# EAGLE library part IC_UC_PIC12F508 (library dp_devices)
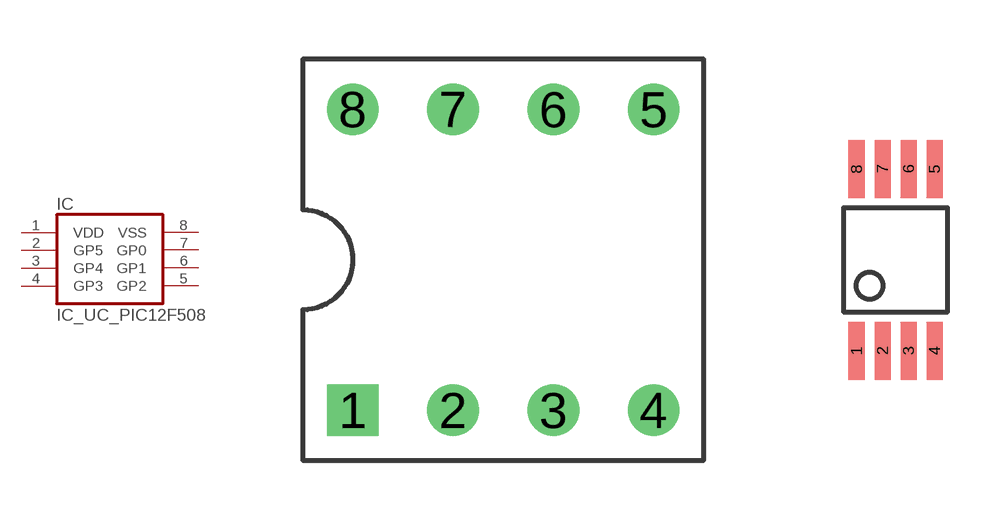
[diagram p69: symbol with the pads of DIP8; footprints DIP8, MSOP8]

Designator prefix IC

## IC_UC_PIC12F508DIP  [DIP8]
1  VDD  pwr
2  GP5
3  GP4
4  GP3
5  GP2
6  GP1
7  GP0
8  VSS  pwr

## IC_UC_PIC12F508MSOP  [MSOP8]
Pads as for DIP8

## IC_UC_PIC12F508SOIC  [SO-8]
Pads as for DIP8

## IC_UC_PIC12F508DFN  [DFN8_3X2]
Pads as for DIP8

## Footprint DIP8 (pad centres in mm)
drill 0.8 square: 1 -3.81,-3.81
drill 0.8 round: 2 -1.27,-3.81; 3 1.27,-3.81; 4 3.81,-3.81; 5 3.81,3.81; 6 1.27,3.81; 7 -1.27,3.81; 8 -3.81,3.81

## Footprint MSOP8 (pad centres in mm)
smd 0.4 x 1.45: 1 -0.975,-2.275; 2 -0.325,-2.275; 3 0.325,-2.275; 4 0.975,-2.275; 5 0.975,2.275; 6 0.325,2.275; 7 -0.325,2.275; 8 -0.975,2.275

## Footprint SO-8 (pad centres in mm)
smd 0.6 x 1.55: 1 -1.905,-2.69; 2 -0.635,-2.69; 3 0.635,-2.69; 4 1.905,-2.69; 5 1.905,2.71; 6 0.635,2.71; 7 -0.635,2.71; 8 -1.905,2.71

## Footprint DFN8_3X2 (pad centres in mm)
smd 0.3 x 0.7: 1 -0.75,-1.5; 2 -0.25,-1.5; 3 0.25,-1.5; 4 0.75,-1.5; 5 0.75,1.5; 6 0.25,1.5; 7 -0.25,1.5; 8 -0.75,1.5
smd 1.75 x 1.45: PAD 0,0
